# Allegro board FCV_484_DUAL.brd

Outline 347.98 x 322.58 mm; copper layers: TOP, SIG1, SIG2, SIG3, BOTTOM. Coordinates in mm from the lower left corner of the outline.
Outline path: rectangle 0,0 347.98,322.58

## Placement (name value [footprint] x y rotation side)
U1  -  [22X22]  173.99 168.17 0 top

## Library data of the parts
U1 = 22X22_0

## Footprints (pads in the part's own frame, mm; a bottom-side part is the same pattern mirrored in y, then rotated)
22X22
  round 0.401 smd: A1(-8.4,8.4) A2(-7.6,8.4) A3(-6.8,8.4) A4(-5.999,8.4) A5(-5.199,8.4) A6(-4.399,8.4) A7(-3.599,8.4) A8(-2.799,8.4) A9(-1.999,8.4) A10(-1.199,8.4) A11(-0.399,8.4) A12(0.399,8.4) A13(1.199,8.4) A14(1.999,8.4) A15(2.799,8.4) A16(3.599,8.4) A17(4.399,8.4) A18(5.199,8.4) A19(5.999,8.4) A20(6.8,8.4) A21(7.6,8.4) A22(8.4,8.4) AA1(-8.4,-7.6) AA2(-7.6,-7.6) AA3(-6.8,-7.6) AA4(-5.999,-7.6) AA5(-5.199,-7.6) AA6(-4.399,-7.6) AA7(-3.599,-7.6) AA8(-2.799,-7.6) AA9(-1.999,-7.6) AA10(-1.199,-7.6) AA11(-0.399,-7.6) AA12(0.399,-7.6) AA13(1.199,-7.6) AA14(1.999,-7.6) AA15(2.799,-7.6) AA16(3.599,-7.6) AA17(4.399,-7.6) AA18(5.199,-7.6) AA19(5.999,-7.6) AA20(6.8,-7.6) AA21(7.6,-7.6) AA22(8.4,-7.6) AB1(-8.4,-8.4) AB2(-7.6,-8.4) AB3(-6.8,-8.4) AB4(-5.999,-8.4) AB5(-5.199,-8.4) AB6(-4.399,-8.4) AB7(-3.599,-8.4) AB8(-2.799,-8.4) AB9(-1.999,-8.4) AB10(-1.199,-8.4) AB11(-0.399,-8.4) AB12(0.399,-8.4) AB13(1.199,-8.4) AB14(1.999,-8.4) AB15(2.799,-8.4) AB16(3.599,-8.4) AB17(4.399,-8.4) AB18(5.199,-8.4) AB19(5.999,-8.4) AB20(6.8,-8.4) AB21(7.6,-8.4) AB22(8.4,-8.4) B1(-8.4,7.6) B2(-7.6,7.6) B3(-6.8,7.6) B4(-5.999,7.6) B5(-5.199,7.6) B6(-4.399,7.6) B7(-3.599,7.6) B8(-2.799,7.6) B9(-1.999,7.6) B10(-1.199,7.6) B11(-0.399,7.6) B12(0.399,7.6) B13(1.199,7.6) B14(1.999,7.6) B15(2.799,7.6) B16(3.599,7.6) B17(4.399,7.6) B18(5.199,7.6) B19(5.999,7.6) B20(6.8,7.6) B21(7.6,7.6) B22(8.4,7.6) C1(-8.4,6.8) C2(-7.6,6.8) C3(-6.8,6.8) C4(-5.999,6.8) C5(-5.199,6.8) C6(-4.399,6.8) C7(-3.599,6.8) C8(-2.799,6.8) C9(-1.999,6.8) C10(-1.199,6.8) C11(-0.399,6.8) C12(0.399,6.8) C13(1.199,6.8) C14(1.999,6.8) C15(2.799,6.8) C16(3.599,6.8) C17(4.399,6.8) C18(5.199,6.8) C19(5.999,6.8) C20(6.8,6.8) C21(7.6,6.8) C22(8.4,6.8) D1(-8.4,5.999) D2(-7.6,5.999) D3(-6.8,5.999) D4(-5.999,5.999) D5(-5.199,5.999) D6(-4.399,5.999) D7(-3.599,5.999) D8(-2.799,5.999) D9(-1.999,5.999) D10(-1.199,5.999) D11(-0.399,5.999) D12(0.399,5.999) D13(1.199,5.999) D14(1.999,5.999) D15(2.799,5.999) D16(3.599,5.999) D17(4.399,5.999) D18(5.199,5.999) D19(5.999,5.999) D20(6.8,5.999) D21(7.6,5.999) D22(8.4,5.999) E1(-8.4,5.199) E2(-7.6,5.199) E3(-6.8,5.199) E4(-5.999,5.199) E5(-5.199,5.199) E6(-4.399,5.199) E7(-3.599,5.199) E8(-2.799,5.199) E9(-1.999,5.199) E10(-1.199,5.199) E11(-0.399,5.199) E12(0.399,5.199) E13(1.199,5.199) E14(1.999,5.199) E15(2.799,5.199) E16(3.599,5.199) E17(4.399,5.199) E18(5.199,5.199) E19(5.999,5.199) E20(6.8,5.199) E21(7.6,5.199) E22(8.4,5.199) F1(-8.4,4.399) F2(-7.6,4.399) F3(-6.8,4.399) F4(-5.999,4.399) F5(-5.199,4.399) F6(-4.399,4.399) F7(-3.599,4.399) F8(-2.799,4.399) F9(-1.999,4.399) F10(-1.199,4.399) F11(-0.399,4.399) F12(0.399,4.399) F13(1.199,4.399) F14(1.999,4.399) F15(2.799,4.399) F16(3.599,4.399) F17(4.399,4.399) F18(5.199,4.399) F19(5.999,4.399) F20(6.8,4.399) F21(7.6,4.399) F22(8.4,4.399) G1(-8.4,3.599) G2(-7.6,3.599) G3(-6.8,3.599) G4(-5.999,3.599) G5(-5.199,3.599) G6(-4.399,3.599) G7(-3.599,3.599) G8(-2.799,3.599) G9(-1.999,3.599) G10(-1.199,3.599) G11(-0.399,3.599) G12(0.399,3.599) G13(1.199,3.599) G14(1.999,3.599) G15(2.799,3.599) G16(3.599,3.599) G17(4.399,3.599) G18(5.199,3.599) G19(5.999,3.599) G20(6.8,3.599) G21(7.6,3.599) G22(8.4,3.599) H1(-8.4,2.799) H2(-7.6,2.799) H3(-6.8,2.799) H4(-5.999,2.799) H5(-5.199,2.799) H6(-4.399,2.799) H7(-3.599,2.799) H8(-2.799,2.799) H9(-1.999,2.799) H10(-1.199,2.799) H11(-0.399,2.799) H12(0.399,2.799) H13(1.199,2.799) H14(1.999,2.799) H15(2.799,2.799) H16(3.599,2.799) H17(4.399,2.799) H18(5.199,2.799) H19(5.999,2.799) H20(6.8,2.799) H21(7.6,2.799) H22(8.4,2.799) J1(-8.4,1.999) J2(-7.6,1.999) J3(-6.8,1.999) J4(-5.999,1.999) J5(-5.199,1.999) J6(-4.399,1.999) J7(-3.599,1.999) J8(-2.799,1.999) J9(-1.999,1.999) J10(-1.199,1.999) J11(-0.399,1.999) J12(0.399,1.999) J13(1.199,1.999) J14(1.999,1.999) J15(2.799,1.999) J16(3.599,1.999) J17(4.399,1.999) J18(5.199,1.999) J19(5.999,1.999) J20(6.8,1.999) J21(7.6,1.999) J22(8.4,1.999) K1(-8.4,1.199) K2(-7.6,1.199) K3(-6.8,1.199) K4(-5.999,1.199) K5(-5.199,1.199) K6(-4.399,1.199) K7(-3.599,1.199) K8(-2.799,1.199) K9(-1.999,1.199) K10(-1.199,1.199) K11(-0.399,1.199) K12(0.399,1.199) K13(1.199,1.199) K14(1.999,1.199) K15(2.799,1.199) K16(3.599,1.199) K17(4.399,1.199) K18(5.199,1.199) K19(5.999,1.199) K20(6.8,1.199) K21(7.6,1.199) K22(8.4,1.199) L1(-8.4,0.399) L2(-7.6,0.399) L3(-6.8,0.399) L4(-5.999,0.399) L5(-5.199,0.399) L6(-4.399,0.399) L7(-3.599,0.399) L8(-2.799,0.399) L9(-1.999,0.399) L10(-1.199,0.399) L11(-0.399,0.399) L12(0.399,0.399) L13(1.199,0.399) L14(1.999,0.399) L15(2.799,0.399) L16(3.599,0.399) L17(4.399,0.399) L18(5.199,0.399) L19(5.999,0.399) L20(6.8,0.399) L21(7.6,0.399) L22(8.4,0.399) M1(-8.4,-0.399) M2(-7.6,-0.399) M3(-6.8,-0.399) M4(-5.999,-0.399) M5(-5.199,-0.399) M6(-4.399,-0.399) M7(-3.599,-0.399) M8(-2.799,-0.399) M9(-1.999,-0.399) M10(-1.199,-0.399) M11(-0.399,-0.399) M12(0.399,-0.399) M13(1.199,-0.399) M14(1.999,-0.399) M15(2.799,-0.399) M16(3.599,-0.399) M17(4.399,-0.399) M18(5.199,-0.399) M19(5.999,-0.399) M20(6.8,-0.399) M21(7.6,-0.399) M22(8.4,-0.399) N1(-8.4,-1.199) N2(-7.6,-1.199) N3(-6.8,-1.199) N4(-5.999,-1.199) N5(-5.199,-1.199) N6(-4.399,-1.199) N7(-3.599,-1.199) N8(-2.799,-1.199) N9(-1.999,-1.199) N10(-1.199,-1.199) N11(-0.399,-1.199) N12(0.399,-1.199) N13(1.199,-1.199) N14(1.999,-1.199) N15(2.799,-1.199) N16(3.599,-1.199) N17(4.399,-1.199) N18(5.199,-1.199) N19(5.999,-1.199) N20(6.8,-1.199) N21(7.6,-1.199) N22(8.4,-1.199) P1(-8.4,-1.999) P2(-7.6,-1.999) P3(-6.8,-1.999) P4(-5.999,-1.999) P5(-5.199,-1.999) P6(-4.399,-1.999) P7(-3.599,-1.999) P8(-2.799,-1.999) P9(-1.999,-1.999) P10(-1.199,-1.999) P11(-0.399,-1.999) P12(0.399,-1.999) P13(1.199,-1.999) P14(1.999,-1.999) P15(2.799,-1.999) P16(3.599,-1.999) P17(4.399,-1.999) P18(5.199,-1.999) P19(5.999,-1.999) P20(6.8,-1.999) P21(7.6,-1.999) P22(8.4,-1.999) R1(-8.4,-2.799) R2(-7.6,-2.799) R3(-6.8,-2.799) R4(-5.999,-2.799) R5(-5.199,-2.799) R6(-4.399,-2.799) R7(-3.599,-2.799) R8(-2.799,-2.799) R9(-1.999,-2.799) R10(-1.199,-2.799) R11(-0.399,-2.799) R12(0.399,-2.799) R13(1.199,-2.799) R14(1.999,-2.799) R15(2.799,-2.799) R16(3.599,-2.799) R17(4.399,-2.799) R18(5.199,-2.799) R19(5.999,-2.799) R20(6.8,-2.799) R21(7.6,-2.799) R22(8.4,-2.799) T1(-8.4,-3.599) T2(-7.6,-3.599) T3(-6.8,-3.599) T4(-5.999,-3.599) T5(-5.199,-3.599) T6(-4.399,-3.599) T7(-3.599,-3.599) T8(-2.799,-3.599) T9(-1.999,-3.599) T10(-1.199,-3.599) T11(-0.399,-3.599) T12(0.399,-3.599) T13(1.199,-3.599) T14(1.999,-3.599) T15(2.799,-3.599) T16(3.599,-3.599) T17(4.399,-3.599) T18(5.199,-3.599) T19(5.999,-3.599) T20(6.8,-3.599) T21(7.6,-3.599) T22(8.4,-3.599) U1(-8.4,-4.399) U2(-7.6,-4.399) U3(-6.8,-4.399) U4(-5.999,-4.399) U5(-5.199,-4.399) U6(-4.399,-4.399) U7(-3.599,-4.399) U8(-2.799,-4.399) U9(-1.999,-4.399) U10(-1.199,-4.399) U11(-0.399,-4.399) U12(0.399,-4.399) U13(1.199,-4.399) U14(1.999,-4.399) U15(2.799,-4.399) U16(3.599,-4.399) U17(4.399,-4.399) U18(5.199,-4.399) U19(5.999,-4.399) U20(6.8,-4.399) U21(7.6,-4.399) U22(8.4,-4.399) V1(-8.4,-5.199) V2(-7.6,-5.199) V3(-6.8,-5.199) V4(-5.999,-5.199) V5(-5.199,-5.199) V6(-4.399,-5.199) V7(-3.599,-5.199) V8(-2.799,-5.199) V9(-1.999,-5.199) V10(-1.199,-5.199) V11(-0.399,-5.199) V12(0.399,-5.199) V13(1.199,-5.199) V14(1.999,-5.199) V15(2.799,-5.199) V16(3.599,-5.199) V17(4.399,-5.199) V18(5.199,-5.199) V19(5.999,-5.199) V20(6.8,-5.199) V21(7.6,-5.199) V22(8.4,-5.199) W1(-8.4,-5.999) W2(-7.6,-5.999) W3(-6.8,-5.999) W4(-5.999,-5.999) W5(-5.199,-5.999) W6(-4.399,-5.999) W7(-3.599,-5.999) W8(-2.799,-5.999) W9(-1.999,-5.999) W10(-1.199,-5.999) W11(-0.399,-5.999) W12(0.399,-5.999) W13(1.199,-5.999) W14(1.999,-5.999) W15(2.799,-5.999) W16(3.599,-5.999) W17(4.399,-5.999) W18(5.199,-5.999) W19(5.999,-5.999) W20(6.8,-5.999) W21(7.6,-5.999) W22(8.4,-5.999) Y1(-8.4,-6.8) Y2(-7.6,-6.8) Y3(-6.8,-6.8) Y4(-5.999,-6.8) Y5(-5.199,-6.8) Y6(-4.399,-6.8) Y7(-3.599,-6.8) Y8(-2.799,-6.8) Y9(-1.999,-6.8) Y10(-1.199,-6.8) Y11(-0.399,-6.8) Y12(0.399,-6.8) Y13(1.199,-6.8) Y14(1.999,-6.8) Y15(2.799,-6.8) Y16(3.599,-6.8) Y17(4.399,-6.8) Y18(5.199,-6.8) Y19(5.999,-6.8) Y20(6.8,-6.8) Y21(7.6,-6.8) Y22(8.4,-6.8)

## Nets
VDD: U1.J13(VDD#J13) U1.K12(VDD#K12) U1.K14(VDD#K14) U1.K16(VDD#K16) U1.L11(VDD#L11) U1.L15(VDD#L15) U1.L17(VDD#L17) U1.M12(VDD#M12) U1.M14(VDD#M14) U1.M16(VDD#M16) U1.N11(VDD#N11) U1.N13(VDD#N13) U1.N15(VDD#N15) U1.N17(VDD#N17)
VDD18: U1.N14(VDD18#N14) U1.P10(VDD18#P10) U1.P12(VDD18#P12) U1.P14(VDD18#P14) U1.P16(VDD18#P16)
VDD25: U1.H8(VDD25#H8) U1.J17(VDD25#J17) U1.L13(VDD25#L13) U1.R9(VDD25#R9) U1.R17(VDD25#R17)
VDDA: U1.G21(VDDA#G21) U1.J21(VDDA#J21) U1.K19(VDDA#K19) U1.L21(VDDA#L21) U1.N21(VDDA#N21) U1.P19(VDDA#P19) U1.R21(VDDA#R21)
VDDA25: U1.J18(VDDA25#J18) U1.N18(VDDA25#N18)
VDDAUX2: U1.H11(VDDAUX2#H11) U1.H14(VDDAUX2#H14) U1.H16(VDDAUX2#H16) U1.J15(VDDAUX2#J15)
VDDAUX4: U1.F4(VDDAUX4#F4) U1.G1(VDDAUX4#G1) U1.K10(VDDAUX4#K10) U1.M10(VDDAUX4#M10) U1.N9(VDDAUX4#N9)
VDDI0: U1.AA9(VDDI0#AA9) U1.AB6(VDDI0#AB6) U1.U1(VDDI0#U1) U1.U11(VDDI0#U11) U1.V8(VDDI0#V8) U1.W5(VDDI0#W5) U1.Y2(VDDI0#Y2)
VDDI1: U1.AA19(VDDI1#AA19) U1.AB16(VDDI1#AB16) U1.T14(VDDI1#T14) U1.V18(VDDI1#V18) U1.W15(VDDI1#W15) U1.Y12(VDDI1#Y12) U1.Y22(VDDI1#Y22)
VDDI2: U1.A9(VDDI2#A9) U1.A19(VDDI2#A19) U1.B6(VDDI2#B6) U1.B16(VDDI2#B16) U1.C3(VDDI2#C3) U1.C13(VDDI2#C13) U1.C21(VDDI2#C21) U1.D10(VDDI2#D10) U1.E7(VDDI2#E7) U1.E17(VDDI2#E17) U1.F14(VDDI2#F14) U1.H13(VDDI2#H13) U1.H17(VDDI2#H17)
VDDI3: U1.G11(VDDI3#G11) U1.J11(VDDI3#J11)
VDDI4: U1.J5(VDDI4#J5) U1.K2(VDDI4#K2) U1.L9(VDDI4#L9) U1.M6(VDDI4#M6) U1.N3(VDDI4#N3) U1.R7(VDDI4#R7) U1.T4(VDDI4#T4)
VDDSREF: U1.L18(VDDSREF#L18) U1.R18(VDDSREF#R18)
VSS: U1.A1(VSS#A1) U1.A4(VSS#A4) U1.A14(VSS#A14) U1.A22(VSS#A22) U1.AA4(VSS#AA4) U1.AA14(VSS#AA14) U1.AB1(VSS#AB1) U1.AB11(VSS#AB11) U1.AB22(VSS#AB22) U1.B11(VSS#B11) U1.C8(VSS#C8) U1.C18(VSS#C18) U1.D5(VSS#D5) U1.D15(VSS#D15) U1.E2(VSS#E2) U1.E12(VSS#E12) U1.F9(VSS#F9) U1.G6(VSS#G6) U1.G16(VSS#G16) U1.H3(VSS#H3) U1.J10(VSS#J10) U1.J12(VSS#J12) U1.J14(VSS#J14) U1.J16(VSS#J16) U1.K7(VSS#K7) U1.K11(VSS#K11) U1.K13(VSS#K13) U1.K15(VSS#K15) U1.K17(VSS#K17) U1.L4(VSS#L4) U1.L10(VSS#L10) U1.L12(VSS#L12) U1.L14(VSS#L14) U1.L16(VSS#L16) U1.M1(VSS#M1) U1.M11(VSS#M11) U1.M13(VSS#M13) U1.M15(VSS#M15) U1.M17(VSS#M17) U1.N10(VSS#N10) U1.N12(VSS#N12) U1.N16(VSS#N16) U1.P5(VSS#P5) U1.P11(VSS#P11) U1.P13(VSS#P13) U1.P15(VSS#P15) U1.P17(VSS#P17) U1.R2(VSS#R2) U1.T9(VSS#T9) U1.U6(VSS#U6) U1.U16(VSS#U16) U1.V3(VSS#V3) U1.V13(VSS#V13) U1.W10(VSS#W10) U1.W20(VSS#W20) U1.Y7(VSS#Y7) U1.Y17(VSS#Y17)
VSSA: U1.E20(VSSA#E20) U1.E21(VSSA#E21) U1.E22(VSSA#E22) U1.F18(VSSA#F18) U1.F19(VSSA#F19) U1.F20(VSSA#F20) U1.G18(VSSA#G18) U1.G22(VSSA#G22) U1.H20(VSSA#H20) U1.J22(VSSA#J22) U1.K18(VSSA#K18) U1.K20(VSSA#K20) U1.L22(VSSA#L22) U1.M18(VSSA#M18) U1.M19(VSSA#M19) U1.M20(VSSA#M20) U1.N22(VSSA#N22) U1.P18(VSSA#P18) U1.P20(VSSA#P20) U1.R22(VSSA#R22) U1.T18(VSSA#T18) U1.T19(VSSA#T19) U1.T20(VSSA#T20) U1.U20(VSSA#U20) U1.U21(VSSA#U21) U1.U22(VSSA#U22)
IO-BANK0_1: U1.R10(IO-BANK0_1)
IO-BANK0_2: U1.R11(IO-BANK0_2)
IO-BANK0_3: U1.R12(IO-BANK0_3)
IO-BANK0_4: U1.T6(IO-BANK0_4)
IO-BANK0_5: U1.T7(IO-BANK0_5)
IO-BANK0_6: U1.T8(IO-BANK0_6)
IO-BANK0_7: U1.T10(IO-BANK0_7)
IO-BANK0_8: U1.T11(IO-BANK0_8)
IO-BANK0_9: U1.U2(IO-BANK0_9)
IO-BANK0_10: U1.U3(IO-BANK0_10)
IO-BANK0_11: U1.U4(IO-BANK0_11)
IO-BANK0_12: U1.U5(IO-BANK0_12)
IO-BANK0_13: U1.U7(IO-BANK0_13)
IO-BANK0_14: U1.U8(IO-BANK0_14)
IO-BANK0_15: U1.U9(IO-BANK0_15)
IO-BANK0_16: U1.U10(IO-BANK0_16)
IO-BANK0_17: U1.V1(IO-BANK0_17)
IO-BANK0_18: U1.V2(IO-BANK0_18)
IO-BANK0_19: U1.V4(IO-BANK0_19)
IO-BANK0_20: U1.V5(IO-BANK0_20)
IO-BANK0_21: U1.V6(IO-BANK0_21)
IO-BANK0_22: U1.V7(IO-BANK0_22)
IO-BANK0_23: U1.V9(IO-BANK0_23)
IO-BANK0_24: U1.V10(IO-BANK0_24)
IO-BANK0_25: U1.V11(IO-BANK0_25)
IO-BANK0_26: U1.W1(IO-BANK0_26)
IO-BANK0_27: U1.W2(IO-BANK0_27)
IO-BANK0_28: U1.W3(IO-BANK0_28)
IO-BANK0_29: U1.W4(IO-BANK0_29)
IO-BANK0_30: U1.W6(IO-BANK0_30)
IO-BANK0_31: U1.W7(IO-BANK0_31)
IO-BANK0_32: U1.W8(IO-BANK0_32)
IO-BANK0_33: U1.W9(IO-BANK0_33)
IO-BANK0_34: U1.W11(IO-BANK0_34)
IO-BANK0_35: U1.Y1(IO-BANK0_35)
IO-BANK0_36: U1.Y3(IO-BANK0_36)
IO-BANK0_37: U1.Y4(IO-BANK0_37)
IO-BANK0_38: U1.Y5(IO-BANK0_38)
IO-BANK0_39: U1.Y6(IO-BANK0_39)
IO-BANK0_40: U1.Y8(IO-BANK0_40)
IO-BANK0_41: U1.Y9(IO-BANK0_41)
IO-BANK0_42: U1.Y10(IO-BANK0_42)
IO-BANK0_43: U1.Y11(IO-BANK0_43)
IO-BANK0_44: U1.AA1(IO-BANK0_44)
IO-BANK0_45: U1.AA2(IO-BANK0_45)
IO-BANK0_46: U1.AA3(IO-BANK0_46)
IO-BANK0_47: U1.AA5(IO-BANK0_47)
IO-BANK0_48: U1.AA6(IO-BANK0_48)
IO-BANK0_49: U1.AA7(IO-BANK0_49)
IO-BANK0_50: U1.AA8(IO-BANK0_50)
IO-BANK0_51: U1.AA10(IO-BANK0_51)
IO-BANK0_52: U1.AA11(IO-BANK0_52)
IO-BANK0_53: U1.AB2(IO-BANK0_53)
IO-BANK0_54: U1.AB3(IO-BANK0_54)
IO-BANK0_55: U1.AB4(IO-BANK0_55)
IO-BANK0_56: U1.AB5(IO-BANK0_56)
IO-BANK0_57: U1.AB7(IO-BANK0_57)
IO-BANK0_58: U1.AB8(IO-BANK0_58)
IO-BANK0_59: U1.AB9(IO-BANK0_59)
IO-BANK0_60: U1.AB10(IO-BANK0_60)
IO-BANK1_1: U1.R13(IO-BANK1_1)
IO-BANK1_2: U1.R14(IO-BANK1_2)
IO-BANK1_3: U1.R15(IO-BANK1_3)
IO-BANK1_4: U1.R16(IO-BANK1_4)
IO-BANK1_5: U1.T12(IO-BANK1_5)
IO-BANK1_6: U1.T13(IO-BANK1_6)
IO-BANK1_7: U1.T15(IO-BANK1_7)
IO-BANK1_8: U1.T16(IO-BANK1_8)
IO-BANK1_9: U1.T17(IO-BANK1_9)
IO-BANK1_10: U1.U12(IO-BANK1_10)
IO-BANK1_11: U1.U13(IO-BANK1_11)
IO-BANK1_12: U1.U14(IO-BANK1_12)
IO-BANK1_13: U1.U15(IO-BANK1_13)
IO-BANK1_14: U1.U17(IO-BANK1_14)
IO-BANK1_15: U1.U18(IO-BANK1_15)
IO-BANK1_16: U1.U19(IO-BANK1_16)
IO-BANK1_17: U1.V12(IO-BANK1_17)
IO-BANK1_18: U1.V14(IO-BANK1_18)
IO-BANK1_19: U1.V15(IO-BANK1_19)
IO-BANK1_20: U1.V16(IO-BANK1_20)
IO-BANK1_21: U1.V17(IO-BANK1_21)
IO-BANK1_22: U1.V19(IO-BANK1_22)
IO-BANK1_23: U1.V20(IO-BANK1_23)
IO-BANK1_24: U1.V21(IO-BANK1_24)
IO-BANK1_25: U1.V22(IO-BANK1_25)
IO-BANK1_26: U1.W12(IO-BANK1_26)
IO-BANK1_27: U1.W13(IO-BANK1_27)
IO-BANK1_28: U1.W14(IO-BANK1_28)
IO-BANK1_29: U1.W16(IO-BANK1_29)
IO-BANK1_30: U1.W17(IO-BANK1_30)
IO-BANK1_31: U1.W18(IO-BANK1_31)
IO-BANK1_32: U1.W19(IO-BANK1_32)
IO-BANK1_33: U1.W21(IO-BANK1_33)
IO-BANK1_34: U1.W22(IO-BANK1_34)
IO-BANK1_35: U1.Y13(IO-BANK1_35)
IO-BANK1_36: U1.Y14(IO-BANK1_36)
IO-BANK1_37: U1.Y15(IO-BANK1_37)
IO-BANK1_38: U1.Y16(IO-BANK1_38)
IO-BANK1_39: U1.Y18(IO-BANK1_39)
IO-BANK1_40: U1.Y19(IO-BANK1_40)
IO-BANK1_41: U1.Y20(IO-BANK1_41)
IO-BANK1_42: U1.Y21(IO-BANK1_42)
IO-BANK1_43: U1.AA12(IO-BANK1_43)
IO-BANK1_44: U1.AA13(IO-BANK1_44)
IO-BANK1_45: U1.AA15(IO-BANK1_45)
IO-BANK1_46: U1.AA16(IO-BANK1_46)
IO-BANK1_47: U1.AA17(IO-BANK1_47)
IO-BANK1_48: U1.AA18(IO-BANK1_48)
IO-BANK1_49: U1.AA20(IO-BANK1_49)
IO-BANK1_50: U1.AA21(IO-BANK1_50)
IO-BANK1_51: U1.AA22(IO-BANK1_51)
IO-BANK1_52: U1.AB12(IO-BANK1_52)
IO-BANK1_53: U1.AB13(IO-BANK1_53)
IO-BANK1_54: U1.AB14(IO-BANK1_54)
IO-BANK1_55: U1.AB15(IO-BANK1_55)
IO-BANK1_56: U1.AB17(IO-BANK1_56)
IO-BANK1_57: U1.AB18(IO-BANK1_57)
IO-BANK1_58: U1.AB19(IO-BANK1_58)
IO-BANK1_59: U1.AB20(IO-BANK1_59)
IO-BANK1_60: U1.AB21(IO-BANK1_60)
IO-BANK2_1: U1.A2(IO-BANK2_1)
IO-BANK2_2: U1.A3(IO-BANK2_2)
IO-BANK2_3: U1.A5(IO-BANK2_3)
IO-BANK2_4: U1.A6(IO-BANK2_4)
IO-BANK2_5: U1.A7(IO-BANK2_5)
IO-BANK2_6: U1.A8(IO-BANK2_6)
IO-BANK2_7: U1.A10(IO-BANK2_7)
IO-BANK2_8: U1.A11(IO-BANK2_8)
IO-BANK2_9: U1.A12(IO-BANK2_9)
IO-BANK2_10: U1.A13(IO-BANK2_10)
IO-BANK2_11: U1.A15(IO-BANK2_11)
IO-BANK2_12: U1.A16(IO-BANK2_12)
IO-BANK2_13: U1.A17(IO-BANK2_13)
IO-BANK2_14: U1.A18(IO-BANK2_14)
IO-BANK2_15: U1.A20(IO-BANK2_15)
IO-BANK2_16: U1.A21(IO-BANK2_16)
IO-BANK2_17: U1.B1(IO-BANK2_17)
IO-BANK2_18: U1.B2(IO-BANK2_18)
IO-BANK2_19: U1.B3(IO-BANK2_19)
IO-BANK2_20: U1.B4(IO-BANK2_20)
IO-BANK2_21: U1.B5(IO-BANK2_21)
IO-BANK2_22: U1.B7(IO-BANK2_22)
IO-BANK2_23: U1.B8(IO-BANK2_23)
IO-BANK2_24: U1.B9(IO-BANK2_24)
IO-BANK2_25: U1.B10(IO-BANK2_25)
IO-BANK2_26: U1.B12(IO-BANK2_26)
IO-BANK2_27: U1.B13(IO-BANK2_27)
IO-BANK2_28: U1.B14(IO-BANK2_28)
IO-BANK2_29: U1.B15(IO-BANK2_29)
IO-BANK2_30: U1.B17(IO-BANK2_30)
IO-BANK2_31: U1.B18(IO-BANK2_31)
IO-BANK2_32: U1.B19(IO-BANK2_32)
IO-BANK2_33: U1.B20(IO-BANK2_33)
IO-BANK2_34: U1.B21(IO-BANK2_34)
IO-BANK2_35: U1.B22(IO-BANK2_35)
IO-BANK2_36: U1.C1(IO-BANK2_36)
IO-BANK2_37: U1.C2(IO-BANK2_37)
IO-BANK2_38: U1.C4(IO-BANK2_38)
IO-BANK2_39: U1.C5(IO-BANK2_39)
IO-BANK2_40: U1.C6(IO-BANK2_40)
IO-BANK2_41: U1.C7(IO-BANK2_41)
IO-BANK2_42: U1.C9(IO-BANK2_42)
IO-BANK2_43: U1.C10(IO-BANK2_43)
IO-BANK2_44: U1.C11(IO-BANK2_44)
IO-BANK2_45: U1.C12(IO-BANK2_45)
IO-BANK2_46: U1.C14(IO-BANK2_46)
IO-BANK2_47: U1.C15(IO-BANK2_47)
IO-BANK2_48: U1.C16(IO-BANK2_48)
IO-BANK2_49: U1.C17(IO-BANK2_49)
IO-BANK2_50: U1.C19(IO-BANK2_50)
IO-BANK2_51: U1.C20(IO-BANK2_51)
IO-BANK2_52: U1.C22(IO-BANK2_52)
IO-BANK2_53: U1.D3(IO-BANK2_53)
IO-BANK2_54: U1.D4(IO-BANK2_54)
IO-BANK2_55: U1.D6(IO-BANK2_55)
IO-BANK2_56: U1.D7(IO-BANK2_56)
IO-BANK2_57: U1.D8(IO-BANK2_57)
IO-BANK2_58: U1.D9(IO-BANK2_58)
IO-BANK2_59: U1.D11(IO-BANK2_59)
IO-BANK2_60: U1.D12(IO-BANK2_60)
IO-BANK2_61: U1.D13(IO-BANK2_61)
IO-BANK2_62: U1.D14(IO-BANK2_62)
IO-BANK2_63: U1.D16(IO-BANK2_63)
IO-BANK2_64: U1.D17(IO-BANK2_64)
IO-BANK2_65: U1.D18(IO-BANK2_65)
IO-BANK2_66: U1.D19(IO-BANK2_66)
IO-BANK2_67: U1.D20(IO-BANK2_67)
IO-BANK2_68: U1.D21(IO-BANK2_68)
IO-BANK2_69: U1.D22(IO-BANK2_69)
IO-BANK2_70: U1.E4(IO-BANK2_70)
IO-BANK2_71: U1.E5(IO-BANK2_71)
IO-BANK2_72: U1.E6(IO-BANK2_72)
IO-BANK2_73: U1.E8(IO-BANK2_73)
IO-BANK2_74: U1.E9(IO-BANK2_74)
IO-BANK2_75: U1.E10(IO-BANK2_75)
IO-BANK2_76: U1.E11(IO-BANK2_76)
IO-BANK2_77: U1.E13(IO-BANK2_77)
IO-BANK2_78: U1.E14(IO-BANK2_78)
IO-BANK2_79: U1.E15(IO-BANK2_79)
IO-BANK2_80: U1.E16(IO-BANK2_80)
IO-BANK2_81: U1.E18(IO-BANK2_81)
IO-BANK2_82: U1.E19(IO-BANK2_82)
IO-BANK2_83: U1.F10(IO-BANK2_83)
IO-BANK2_84: U1.F11(IO-BANK2_84)
IO-BANK2_85: U1.F12(IO-BANK2_85)
IO-BANK2_86: U1.F13(IO-BANK2_86)
IO-BANK2_87: U1.F15(IO-BANK2_87)
IO-BANK2_88: U1.F16(IO-BANK2_88)
IO-BANK2_89: U1.F17(IO-BANK2_89)
IO-BANK2_90: U1.G12(IO-BANK2_90)
IO-BANK2_91: U1.G13(IO-BANK2_91)
IO-BANK2_92: U1.G14(IO-BANK2_92)
IO-BANK2_93: U1.G15(IO-BANK2_93)
IO-BANK2_94: U1.G17(IO-BANK2_94)
IO-BANK2_95: U1.H12(IO-BANK2_95)
IO-BANK2_96: U1.H15(IO-BANK2_96)
IO-BANK4_1: U1.H1(IO-BANK4_1)
IO-BANK4_2: U1.H2(IO-BANK4_2)
IO-BANK4_3: U1.J1(IO-BANK4_3)
IO-BANK4_4: U1.J2(IO-BANK4_4)
IO-BANK4_5: U1.J3(IO-BANK4_5)
IO-BANK4_6: U1.J4(IO-BANK4_6)
IO-BANK4_7: U1.J6(IO-BANK4_7)
IO-BANK4_8: U1.J7(IO-BANK4_8)
IO-BANK4_9: U1.J8(IO-BANK4_9)
IO-BANK4_10: U1.J9(IO-BANK4_10)
IO-BANK4_11: U1.K1(IO-BANK4_11)
IO-BANK4_12: U1.K3(IO-BANK4_12)
IO-BANK4_13: U1.K4(IO-BANK4_13)
IO-BANK4_14: U1.K5(IO-BANK4_14)
IO-BANK4_15: U1.K6(IO-BANK4_15)
IO-BANK4_16: U1.K8(IO-BANK4_16)
IO-BANK4_17: U1.K9(IO-BANK4_17)
IO-BANK4_18: U1.L1(IO-BANK4_18)
IO-BANK4_19: U1.L2(IO-BANK4_19)
IO-BANK4_20: U1.L3(IO-BANK4_20)
IO-BANK4_21: U1.L5(IO-BANK4_21)
IO-BANK4_22: U1.L6(IO-BANK4_22)
IO-BANK4_23: U1.L7(IO-BANK4_23)
IO-BANK4_24: U1.L8(IO-BANK4_24)
IO-BANK4_25: U1.M2(IO-BANK4_25)
IO-BANK4_26: U1.M3(IO-BANK4_26)
IO-BANK4_27: U1.M4(IO-BANK4_27)
IO-BANK4_28: U1.M5(IO-BANK4_28)
IO-BANK4_29: U1.M7(IO-BANK4_29)
IO-BANK4_30: U1.M8(IO-BANK4_30)
IO-BANK4_31: U1.M9(IO-BANK4_31)
IO-BANK4_32: U1.N1(IO-BANK4_32)
IO-BANK4_33: U1.N2(IO-BANK4_33)
IO-BANK4_34: U1.N4(IO-BANK4_34)
IO-BANK4_35: U1.N5(IO-BANK4_35)
IO-BANK4_36: U1.N6(IO-BANK4_36)
IO-BANK4_37: U1.N7(IO-BANK4_37)
IO-BANK4_38: U1.N8(IO-BANK4_38)
IO-BANK4_39: U1.P1(IO-BANK4_39)
IO-BANK4_40: U1.P2(IO-BANK4_40)
IO-BANK4_41: U1.P3(IO-BANK4_41)
IO-BANK4_42: U1.P4(IO-BANK4_42)
IO-BANK4_43: U1.P6(IO-BANK4_43)
IO-BANK4_44: U1.P7(IO-BANK4_44)
IO-BANK4_45: U1.P8(IO-BANK4_45)
IO-BANK4_46: U1.P9(IO-BANK4_46)
IO-BANK4_47: U1.R1(IO-BANK4_47)
IO-BANK4_48: U1.R3(IO-BANK4_48)
IO-BANK4_49: U1.R4(IO-BANK4_49)
IO-BANK4_50: U1.R5(IO-BANK4_50)
IO-BANK4_51: U1.R6(IO-BANK4_51)
IO-BANK4_52: U1.R8(IO-BANK4_52)
IO-BANK4_53: U1.T1(IO-BANK4_53)
IO-BANK4_54: U1.T2(IO-BANK4_54)
IO-BANK4_55: U1.T3(IO-BANK4_55)
IO-BANK4_56: U1.T5(IO-BANK4_56)
IO-BANK5_1: U1.D1(IO-BANK5_1)
IO-BANK5_2: U1.D2(IO-BANK5_2)
IO-BANK5_3: U1.E1(IO-BANK5_3)
IO-BANK5_4: U1.E3(IO-BANK5_4)
IO-BANK5_5: U1.F1(IO-BANK5_5)
IO-BANK5_6: U1.F2(IO-BANK5_6)
IO-BANK5_7: U1.F3(IO-BANK5_7)
IO-BANK5_8: U1.F5(IO-BANK5_8)
IO-BANK5_9: U1.G2(IO-BANK5_9)
IO-BANK5_10: U1.G3(IO-BANK5_10)
IO-BANK5_11: U1.G4(IO-BANK5_11)
IO-BANK5_12: U1.G5(IO-BANK5_12)
JTAG-IO_1: U1.F6(JTAG-IO_1)
JTAG-IO_2: U1.F7(JTAG-IO_2)
JTAG-IO_3: U1.F8(JTAG-IO_3)
JTAG-IO_4: U1.G7(JTAG-IO_4)
JTAG-IO_5: U1.G8(JTAG-IO_5)
JTAG-IO_6: U1.G9(JTAG-IO_6)
JTAG-IO_7: U1.G10(JTAG-IO_7)
JTAG-IO_8: U1.H4(JTAG-IO_8)
JTAG-IO_9: U1.H5(JTAG-IO_9)
JTAG-IO_10: U1.H6(JTAG-IO_10)
JTAG-IO_11: U1.H7(JTAG-IO_11)
JTAG-IO_12: U1.H9(JTAG-IO_12)
JTAG-IO_13: U1.H10(JTAG-IO_13)
REFCLK0_1: U1.N19(REFCLK0_1)
REFCLK0_2: U1.N20(REFCLK0_2)
REFCLK1_1: U1.L19(REFCLK1_1)
REFCLK1_2: U1.L20(REFCLK1_2)
REFCLK2_1: U1.J19(REFCLK2_1)
REFCLK2_2: U1.J20(REFCLK2_2)
RX0_1: U1.R19(RX0_1)
RX0_2: U1.R20(RX0_2)
RX1_1: U1.M21(RX1_1)
RX1_2: U1.M22(RX1_2)
RX2_1: U1.K21(RX2_1)
RX2_2: U1.K22(RX2_2)
RX3_1: U1.G19(RX3_1)
RX3_2: U1.G20(RX3_2)
SERDES_VREF: U1.H18(SERDES_VREF#H18) U1.H19(SERDES_VREF#H19)
TX0_1: U1.T21(TX0_1)
TX0_2: U1.T22(TX0_2)
TX1_1: U1.P21(TX1_1)
TX1_2: U1.P22(TX1_2)
TX2_1: U1.H21(TX2_1)
TX2_2: U1.H22(TX2_2)
TX3_1: U1.F21(TX3_1)
TX3_2: U1.F22(TX3_2)

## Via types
v1: diameter 0.457, hole 0.254, TOP to BOTTOM, 312 vias

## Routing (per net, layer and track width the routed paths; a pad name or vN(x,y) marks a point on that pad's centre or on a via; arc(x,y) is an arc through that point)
VDD: length 7.9
  TOP w0.381: U1.L15 v1(177.19,168.97) ; U1.M14 v1(176.39,167.37) ; U1.J13 v1(175.59,170.57) ; U1.L17 v1(178.79,168.97) ; U1.N13 v1(175.59,166.57) ; U1.K12 v1(174.79,169.77) ; U1.N15 v1(177.19,166.57) ; U1.N11 v1(173.19,166.57) ; U1.N17 v1(178.79,166.57) ; U1.L11 v1(173.19,168.97) ; U1.K14 v1(176.39,169.77) ; U1.M16 v1(177.99,167.37) ; U1.M12 v1(174.79,167.37) ; U1.K16 v1(177.99,169.77)
VDD18: length 2.8
  TOP w0.381: U1.P10 v1(172.39,165.77) ; U1.N14 v1(176.39,166.57) ; U1.P12 v1(174.79,165.77) ; U1.P16 v1(177.99,165.77) ; U1.P14 v1(176.39,165.77)
VDD25: length 2.8
  TOP w0.381: U1.R17 v1(178.79,164.97) ; U1.L13 v1(175.59,168.97) ; U1.H8 v1(170.79,171.37) ; U1.J17 v1(178.79,170.57) ; U1.R9 v1(171.59,164.97)
VDDA: length 4
  TOP w0.127: U1.L21 v1(181.99,168.97)
  TOP w0.381: U1.N21 v1(181.99,166.57) ; U1.G21 v1(181.99,172.17) ; U1.K19 v1(180.39,169.77) ; U1.R21 v1(181.99,164.97) ; U1.J21 v1(181.99,170.57) ; U1.P19 v1(180.39,165.77)
VDDA25: length 1.1
  TOP w0.381: U1.J18 v1(179.59,170.57) ; U1.N18 v1(179.59,166.57)
VDDAUX2: length 2.3
  TOP w0.381: U1.H16 v1(177.99,171.37) ; U1.H14 v1(176.39,171.37) ; U1.H11 v1(173.19,171.37) ; U1.J15 v1(177.19,170.57)
VDDAUX4: length 3
  TOP w0.381: U1.G1 v1(164.9,171.77) ; U1.N9 v1(171.59,166.57) ; U1.K10 v1(172.39,169.77) ; U1.M10 v1(172.39,167.37) ; U1.F4 v1(167.59,172.97)
VDDI0: length 4.2
  TOP w0.127: U1.V8 v1(170.79,162.57)
  TOP w0.381: U1.U1 v1(164.9,163.77) ; U1.W5 v1(168.39,161.77) ; U1.AA9 v1(171.59,160.17) ; U1.U11 v1(173.19,163.37) ; U1.AB6 v1(169.59,159.08) ; U1.Y2 v1(165.99,160.97)
VDDI1: length 4.2
  TOP w0.381: U1.W15 v1(177.19,161.77) ; U1.AA19 v1(180.39,160.17) ; U1.AB16 v1(177.59,159.08) ; U1.Y12 v1(174.79,160.97) ; U1.V18 v1(179.59,162.57) ; U1.T14 v1(176.39,164.17) ; U1.Y22 v1(183.08,161.37)
VDDI2: length 7.6
  TOP w0.381: U1.F14 v1(176.39,172.97) ; U1.B6 v1(169.19,175.37) ; U1.H13 v1(175.59,171.37) ; U1.B16 v1(177.99,176.17) ; U1.A19 v1(179.99,177.27) ; U1.E7 v1(169.99,173.77) ; U1.D10 v1(172.39,174.57) ; U1.H17 v1(178.79,171.37) ; U1.C3 v1(166.79,175.37) ; U1.C21 v1(181.99,175.37) ; U1.C13 v1(175.59,175.37) ; U1.E17 v1(178.79,173.77) ; U1.A9 v1(171.99,177.27)
VDDI3: length 1.1
  TOP w0.381: U1.J11 v1(173.19,170.57) ; U1.G11 v1(173.19,172.17)
VDDI4: length 4
  TOP w0.127: U1.N3 v1(166.79,166.57)
  TOP w0.381: U1.M6 v1(169.19,167.37) ; U1.L9 v1(171.59,168.97) ; U1.T4 v1(167.59,164.17) ; U1.R7 v1(169.99,164.97) ; U1.K2 v1(165.99,169.77) ; U1.J5 v1(168.39,170.57)
VDDSREF: length 1.1
  TOP w0.381: U1.R18 v1(179.59,164.97) ; U1.L18 v1(179.59,168.97)
VSS: length 33.4
  TOP w0.127: U1.G16 v1(177.99,172.17) ; U1.W20 v1(181.19,161.77) ; U1.W10 v1(172.39,161.77)
  TOP w0.381: U1.K7 v1(169.99,169.77) ; U1.E2 v1(165.99,173.77) ; U1.L12 v1(174.79,168.97) ; U1.M17 v1(178.79,167.37) ; U1.N16 v1(177.99,166.57) ; U1.C8 v1(170.79,175.37) ; U1.T9 v1(171.59,164.17) ; U1.N10 v1(172.39,166.57) ; U1.AB11 v1(173.59,159.08) ; U1.A14 v1(175.99,177.27) ; U1.K17 v1(178.79,169.77) ; U1.M11 v1(173.19,167.37) ; U1.Y7 v1(169.99,160.97) ; U1.P5 v1(168.39,165.77) ; U1.G6 v1(169.19,172.17) ; U1.H3 v1(166.79,171.37) ; U1.M15 v1(177.19,167.37) ; U1.R2 v1(165.99,164.97) ; U1.Y17 v1(178.79,160.97) ; U1.AA4 v1(167.59,160.17) ; U1.V13 v1(175.59,162.57) ; U1.A1 v1(165.59,177.27) ; U1.P11 v1(173.19,165.77) ; U1.K15 v1(177.19,169.77) ; U1.E12 v1(174.79,173.77) ; U1.J14 v1(176.39,170.57) ; U1.A22 v1(182.39,177.27) ; U1.K13 v1(175.59,169.77) ; U1.J16 v1(177.99,170.57) ; U1.A4 v1(167.99,177.27) ; U1.P13 v1(175.59,165.77) ; U1.V3 v1(166.79,162.57) ; U1.N12 v1(174.79,166.57) ; U1.AB22 v1(182.39,159.08) ; U1.AA14 v1(176.39,160.17) ; U1.L4 v1(167.59,168.97) ; U1.D15 v1(177.19,174.57) ; U1.B11 v1(173.19,176.17) ; U1.P17 v1(178.79,165.77) ; U1.L16 v1(177.99,168.97) ; U1.L14 v1(176.39,168.97) ; U1.P15 v1(177.19,165.77) ; U1.M13 v1(175.59,167.37) ; U1.K11 v1(173.19,169.77) ; U1.L10 v1(172.39,168.97) ; U1.J12 v1(174.79,170.57) ; U1.AB1 v1(164.9,159.77) ; U1.C18 v1(179.59,175.37) ; U1.U16 v1(177.99,163.37) ; U1.J10 v1(172.39,170.57) ; U1.M1 v1(164.9,167.77) ; U1.U6 v1(169.19,163.37) ; U1.D5 v1(168.39,174.57) ; U1.F9 v1(171.59,172.97)
VSSA: length 15.6
  TOP w0.381: U1.R22 v1(183.08,165.37) ; U1.T18 v1(179.59,164.17) ; U1.M19 v1(179.59,168.18) ; U1.M18 v1(179.59,167.37) ; U1.T19 v1(180.39,164.17) ; U1.L22 v1(183.08,168.57) ; U1.E21 v1(181.99,173.77) ; U1.E20 v1(181.19,173.77) ; U1.U22 v1(183.08,163.77) ; U1.J22 v1(183.08,170.17) ; U1.U20 v1(181.19,163.37) ; U1.G22 v1(183.08,171.77) ; U1.F20 v1(181.19,172.97) ; U1.T20 v1(181.19,164.17) ; U1.E22 v1(183.08,173.37) ; U1.F18 v1(179.59,172.97) ; U1.K18 v1(179.59,169.77) ; U1.P18 v1(179.59,165.77) ; U1.F19 v1(180.39,172.97) ; U1.H20 v1(181.19,171.37) ; U1.P20 v1(181.19,165.77) ; U1.G18 v1(179.59,172.17) ; U1.N22 v1(183.08,166.97) ; U1.U21 v1(181.99,163.37) ; U1.M20 v1(180.39,168.18) ; U1.K20 v1(181.19,169.77)
IO-BANK0_1: length 7.6
  TOP w0.127: U1.R10 v1(172.39,164.97)
  SIG2 w0.076: 173.1,159.06 173.1,160.67 173.63,161.2 173.63,164.35 173.41,164.57 172.79,164.57 v1(172.39,164.97)
IO-BANK0_2: length 6.5
  TOP w0.127: U1.R11 v1(173.19,164.97)
  SIG2 w0.076: 173.87,159.51 173.87,164.64 173.54,164.97 v1(173.19,164.97)
IO-BANK0_3: length 6.3
  TOP w0.127: U1.R12 v1(174.79,164.97)
  SIG2 w0.076: v1(174.79,164.97) 174.11,164.3 174.11,159.51
IO-BANK0_4: length 7.2
  TOP w0.127: U1.T6 v1(169.19,164.17)
  SIG1 w0.076: 164.52,161.58 167.63,161.58 168.19,162.15 168.61,162.15 168.78,162.31 168.78,163.76 v1(169.19,164.17)
IO-BANK0_5: length 7.1
  TOP w0.127: U1.T7 v1(169.99,164.17)
  SIG2 w0.076: v1(169.99,164.17) 169.58,163.76 169.58,160.47 169.25,160.13 169.25,158.44 169.58,158.1
IO-BANK0_6: length 6
  TOP w0.127: U1.T8 v1(170.79,164.17)
  SIG2 w0.076: v1(170.79,164.17) 170.37,163.75 170.37,158.87
IO-BANK0_7: length 6.1
  TOP w0.127: U1.T10 v1(172.39,164.17)
  SIG2 w0.076: v1(172.39,164.17) 172.8,163.76 172.8,158.83
IO-BANK0_8: length 6.5
  TOP w0.127: U1.T11 v1(173.19,164.17)
  SIG1 w0.076: v1(173.19,164.17) 173.19,164.08 174,163.28 174,160.4 174.43,159.97 174.43,158.75
IO-BANK0_9: length 2.2
  TOP w0.076: 164.37,163.39 165.1,163.39 165.18,163.46 165.76,163.46 166.08,163.77 U1.U2
IO-BANK0_10: length 3
  TOP w0.076: 164.4,163.18 165.12,163.18 165.25,163.31 165.98,163.31 166.09,163.42 166.83,163.42 U1.U3
IO-BANK0_11: length 3.9
  TOP w0.127: U1.U4 v1(167.59,163.37)
  SIG1 w0.076: v1(167.59,163.37) 165.86,163.37 165.34,162.85 164.52,162.85
IO-BANK0_12: length 4.8
  TOP w0.127: U1.U5 v1(168.39,163.37)
  SIG1 w0.076: 164.48,162.6 165.57,162.6 165.95,162.99 168,162.99 v1(168.39,163.37)
IO-BANK0_13: length 5.4
  TOP w0.127: U1.U7 v1(169.99,163.37)
  SIG1 w0.076: 170.56,158.76 170.56,161.27 170.37,161.46 170.37,162.99 v1(169.99,163.37)
IO-BANK0_14: length 5.3
  TOP w0.127: U1.U8 v1(170.79,163.37)
  SIG2 w0.076: v1(170.79,163.37) 171.19,162.97 171.19,158.83
IO-BANK0_15: length 5.5
  TOP w0.127: U1.U9 v1(171.59,163.37)
  SIG1 w0.076: 172.4,158.76 172.4,160.69 171.98,161.1 171.98,162.98 v1(171.59,163.37)
IO-BANK0_16: length 6.5
  TOP w0.127: U1.U10 v1(172.39,163.37)
  SIG1 w0.076: v1(172.39,163.37) 172.39,163.37 172.76,162.99 173.48,162.99 173.79,162.68 173.79,160.16 174.23,159.72 174.23,158.6
IO-BANK0_17: length 1.2
  TOP w0.076: U1.V1 164.39,162.97
IO-BANK0_18: length 2.1
  TOP w0.076: U1.V2 166.07,162.66 164.41,162.66
IO-BANK0_19: length 3.8
  TOP w0.127: U1.V4 v1(167.59,162.57)
  SIG1 w0.076: 164.52,162.22 167.24,162.22 v1(167.59,162.57)
IO-BANK0_20: length 4.7
  TOP w0.127: U1.V5 v1(168.39,162.57)
  SIG1 w0.076: v1(168.39,162.57) 168.15,162.57 167.52,161.95 164.55,161.95
IO-BANK0_21: length 4.7
  TOP w0.127: U1.V6 v1(169.19,162.57)
  SIG1 w0.076: 168.48,158.7 168.48,159.89 168.78,160.19 168.78,161.98 169.19,162.38 v1(169.19,162.57)
IO-BANK0_22: length 4.8
  TOP w0.127: U1.V7 v1(169.99,162.57)
  SIG1 w0.076: 170,158.67 170,159.34 169.62,159.73 169.62,162.2 v1(169.99,162.57)
IO-BANK0_23: length 4.6
  TOP w0.127: U1.V9 v1(171.59,162.57)
  SIG1 w0.076: 171.18,158.75 171.18,162.17 v1(171.59,162.57)
IO-BANK0_24: length 4.5
  TOP w0.127: U1.V10 v1(172.39,162.57)
  SIG1 w0.076: v1(172.39,162.57) 172.79,162.17 172.79,158.77
IO-BANK0_25: length 4.9
  TOP w0.127: U1.V11 v1(173.19,162.57)
  SIG1 w0.076: 174.01,158.58 174.01,159.44 173.61,159.84 173.61,162.16 v1(173.19,162.57)
IO-BANK0_26: length 1.2
  TOP w0.076: U1.W1 164.39,162.17
IO-BANK0_27: length 2.1
  TOP w0.076: 164.39,162.49 166.07,162.49 U1.W2
IO-BANK0_28: length 2.9
  TOP w0.076: U1.W3 166.88,162.17 166.56,161.86 164.41,161.86
IO-BANK0_29: length 3.8
  TOP w0.076: U1.W4 167.63,161.82 166.89,161.82 166.78,161.71 164.41,161.71
IO-BANK0_30: length 3.7
  TOP w0.127: U1.W6 v1(169.19,161.77)
  SIG1 w0.076: v1(169.19,161.77) 169.19,160.06 168.85,159.71 168.85,158.76
IO-BANK0_31: length 3.8
  TOP w0.127: U1.W7 v1(169.99,161.77)
  SIG1 w0.076: 170.36,158.72 170.36,161.17 169.99,161.54 v1(169.99,161.77)
IO-BANK0_32: length 3.6
  TOP w0.127: U1.W8 v1(170.79,161.77)
  SIG1 w0.076: v1(170.79,161.77) 170.79,158.72
IO-BANK0_33: length 3.9
  TOP w0.127: U1.W9 v1(171.59,161.77)
  SIG1 w0.076: 172.06,158.67 172.06,160.5 171.59,160.97 v1(171.59,161.77)
IO-BANK0_34: length 3.5
  TOP w0.127: U1.W11 v1(173.19,161.77)
  SIG1 w0.076: v1(173.19,161.77) 173.19,158.87
IO-BANK0_35: length 1.2
  TOP w0.076: U1.Y1 164.39,161.37
IO-BANK0_36: length 3.4
  TOP w0.076: U1.Y3 166.72,160.9 166.72,160.38 166.5,160.15 166.25,160.15 165.99,159.9 165.99,158.65
IO-BANK0_37: length 3.6
  TOP w0.076: U1.Y4 167.59,160.97 167.14,160.97 166.87,160.7 166.87,160.28 166.71,160.11 166.71,159.49 166.62,159.41 166.62,158.58
IO-BANK0_38: length 3
  TOP w0.076: 168.31,158.54 168.31,160.89 U1.Y5
IO-BANK0_39: length 3
  TOP w0.076: U1.Y6 169.12,160.9 169.12,159.53 168.98,159.4 168.98,158.59
IO-BANK0_40: length 3
  TOP w0.076: 170.72,158.56 170.72,160.91 U1.Y8
IO-BANK0_41: length 3
  TOP w0.076: 172.32,158.55 172.32,161.05 172,161.37 U1.Y9
IO-BANK0_42: length 3
  TOP w0.076: 172.47,158.55 172.47,161.05 U1.Y10
IO-BANK0_43: length 2.9
  TOP w0.076: U1.Y11 173.91,161.06 173.91,159.3 173.97,159.23 173.97,158.63
IO-BANK0_44: length 1.2
  TOP w0.076: U1.AA1 164.39,160.57
IO-BANK0_45: length 2.2
  TOP w0.076: U1.AA2 166,160.18 164.35,160.18
IO-BANK0_46: length 2.1
  TOP w0.076: 166.87,158.57 166.87,160 167.19,160.32 U1.AA3
IO-BANK0_47: length 2.1
  TOP w0.076: 168.48,158.57 168.48,160.26 U1.AA5
IO-BANK0_48: length 2.2
  TOP w0.076: 169.19,158.57 169.19,159.26 169.28,159.35 169.28,160.26 U1.AA6
IO-BANK0_49: length 2.2
  TOP w0.076: U1.AA7 170,160.18 170,158.57
IO-BANK0_50: length 2.1
  TOP w0.076: U1.AA8 170.88,160.26 170.88,158.57
IO-BANK0_51: length 2.2
  TOP w0.076: 172.98,158.59 172.98,159.42 173.11,159.55 173.11,160.26 U1.AA10
IO-BANK0_52: length 2.2
  TOP w0.076: 173.16,158.56 173.16,159.31 173.28,159.42 173.28,160.26 U1.AA11
IO-BANK0_53: length 1.2
  TOP w0.076: U1.AB2 166.39,158.6
IO-BANK0_54: length 1.2
  TOP w0.076: U1.AB3 167.19,158.6
IO-BANK0_55: length 1.2
  TOP w0.076: U1.AB4 167.99,158.6
IO-BANK0_56: length 1.2
  TOP w0.076: U1.AB5 168.79,158.6
IO-BANK0_57: length 1.2
  TOP w0.076: U1.AB7 170.39,158.6
IO-BANK0_58: length 1.2
  TOP w0.076: U1.AB8 171.19,158.6
IO-BANK0_59: length 1.2
  TOP w0.076: U1.AB9 171.99,158.6
IO-BANK0_60: length 1.2
  TOP w0.076: U1.AB10 172.79,158.6
IO-BANK1_1: length 6.8
  TOP w0.127: U1.R13 v1(175.59,164.97)
  SIG2 w0.076: v1(175.59,164.97) 176,164.56 176,158.87
IO-BANK1_2: length 7.6
  TOP w0.127: U1.R14 v1(176.39,164.97)
  SIG2 w0.076: 177.03,158.82 177.03,159.46 177.6,160.03 177.6,163.49 177.35,163.74 177.03,163.74 176.76,164 176.76,164.6 v1(176.39,164.97)
IO-BANK1_3: length 7
  TOP w0.127: U1.R15 v1(177.19,164.97)
  SIG2 w0.076: 183.41,164.54 177.62,164.54 v1(177.19,164.97)
IO-BANK1_4: length 6.3
  TOP w0.127: U1.R16 v1(177.99,164.97)
  SIG2 w0.076: v1(177.99,164.97) 178.38,165.37 182.34,165.37 182.73,164.98 183.4,164.98
IO-BANK1_5: length 6
  TOP w0.127: U1.T12 v1(174.79,164.17)
  SIG2 w0.076: v1(174.79,164.17) 174.36,163.75 174.36,160.78 174.69,160.46 174.69,159.08
IO-BANK1_6: length 6
  TOP w0.127: U1.T13 v1(175.59,164.17)
  SIG2 w0.076: v1(175.59,164.17) 175.2,163.78 175.2,158.88
IO-BANK1_7: length 6.9
  TOP w0.127: U1.T15 v1(177.19,164.17)
  SIG2 w0.076: 178.06,158.76 178.06,159.44 178.38,159.76 178.38,163.51 178.12,163.78 177.59,163.78 v1(177.19,164.17)
IO-BANK1_8: length 6.7
  TOP w0.127: U1.T16 v1(177.99,164.17)
  SIG2 w0.076: v1(177.99,164.17) 178.15,164.17 178.54,163.78 182.25,163.78 182.84,163.18 183.69,163.18
IO-BANK1_9: length 6.2
  TOP w0.127: U1.T17 v1(178.79,164.17)
  SIG1 w0.076: 183.45,162.65 180.12,162.65 179.79,162.98 179.44,162.98 179.19,163.23 179.19,163.81 178.82,164.17 v1(178.79,164.17)
IO-BANK1_10: length 5.7
  TOP w0.127: U1.U12 v1(174.79,163.37)
  SIG1 w0.076: v1(174.79,163.37) 174.75,163.37 174.19,162.81 174.19,160.61 174.66,160.14 174.66,158.69
IO-BANK1_11: length 5.3
  TOP w0.127: U1.U13 v1(175.59,163.37)
  SIG1 w0.076: 175.19,158.79 175.19,162.97 v1(175.59,163.37)
IO-BANK1_12: length 5.4
  TOP w0.127: U1.U14 v1(176.39,163.37)
  SIG2 w0.076: 176.58,158.85 176.58,159.6 176.8,159.81 176.8,162.97 v1(176.39,163.37)
IO-BANK1_13: length 5.6
  TOP w0.127: U1.U15 v1(177.19,163.37)
  SIG1 w0.076: 177.15,158.71 177.15,159.74 177.56,160.15 177.56,163 v1(177.19,163.37)
IO-BANK1_14: length 6.1
  TOP w0.127: U1.U17 v1(178.79,163.37)
  SIG1 w0.076: v1(178.79,163.37) 179.15,163.01 179.15,162.43 179.39,162.19 183.47,162.19
IO-BANK1_15: length 4.6
  TOP w0.127: U1.U18 v1(179.59,163.37)
  SIG1 w0.076: 183.45,162.98 180.19,162.98 179.8,163.37 v1(179.59,163.37)
IO-BANK1_16: length 4
  TOP w0.127: U1.U19 v1(180.39,163.37)
  SIG1 w0.076: 183.44,163.36 182.64,163.36 182.22,163.78 180.8,163.78 v1(180.39,163.37)
IO-BANK1_17: length 4.7
  TOP w0.127: U1.V12 v1(174.79,162.57)
  SIG1 w0.076: 174.89,158.87 174.89,160.22 174.36,160.74 174.36,162.15 v1(174.79,162.57)
IO-BANK1_18: length 4.7
  TOP w0.127: U1.V14 v1(176.39,162.57)
  SIG1 w0.076: 175.6,158.73 175.6,161.14 175.98,161.51 175.98,162.16 v1(176.39,162.57)
IO-BANK1_19: length 4.5
  TOP w0.127: U1.V15 v1(177.19,162.57)
  SIG1 w0.076: 176.81,158.77 176.81,162.19 v1(177.19,162.57)
IO-BANK1_20: length 4.6
  TOP w0.127: U1.V16 v1(177.99,162.57)
  SIG1 w0.076: v1(177.99,162.57) 178.37,162.19 178.37,161.46 178.22,161.31 178.22,158.75
IO-BANK1_21: length 4.5
  TOP w0.127: U1.V17 v1(178.79,162.57)
  SIG1 w0.076: 179.18,158.79 179.18,161.99 178.79,162.38 v1(178.79,162.57)
IO-BANK1_22: length 4.2
  TOP w0.076: 183.48,161.97 182.75,161.97 182.64,161.86 182.2,161.86 181.98,162.08 181.98,162.35 181.82,162.51 180.46,162.51 U1.V19
IO-BANK1_23: length 2.9
  TOP w0.076: 183.51,162.5 182.07,162.5 181.91,162.66 181.1,162.66 U1.V20
IO-BANK1_24: length 2
  TOP w0.076: 183.49,162.66 182.22,162.66 181.91,162.97 U1.V21
IO-BANK1_25: length 1.1
  TOP w0.076: U1.V22 183.48,162.97
IO-BANK1_26: length 3.7
  TOP w0.076: U1.W12 174.07,161.85 174.07,159.45 174.18,159.33 174.18,158.63
IO-BANK1_27: length 3.7
  TOP w0.127: U1.W13 v1(175.59,161.77)
  SIG1 w0.076: v1(175.59,161.77) 175.38,161.56 175.38,158.77
IO-BANK1_28: length 3.8
  TOP w0.127: U1.W14 v1(176.39,161.77)
  SIG1 w0.076: 175.83,158.75 175.83,160.98 176.39,161.54 v1(176.39,161.77)
IO-BANK1_29: length 3.6
  TOP w0.127: U1.W16 v1(177.99,161.77)
  SIG1 w0.076: v1(177.99,161.77) 177.99,158.76
IO-BANK1_30: length 3.7
  TOP w0.127: U1.W17 v1(178.79,161.77)
  SIG1 w0.076: 178.42,158.76 178.42,161.17 178.79,161.54 v1(178.79,161.77)
IO-BANK1_31: length 3.5
  TOP w0.127: U1.W18 v1(179.59,161.77)
  SIG1 w0.076: v1(179.59,161.77) 179.59,158.79
IO-BANK1_32: length 4.3
  TOP w0.076: U1.W19 180.39,161.77 180.39,161.12 180.56,160.95 180.91,160.95 181.16,160.71 181.16,160.47 181.27,160.36 181.27,158.61 181.29,158.59
IO-BANK1_33: length 2.2
  TOP w0.076: 183.52,161.78 182.81,161.78 182.74,161.71 182.06,161.71 U1.W21
IO-BANK1_34: length 1.1
  TOP w0.076: U1.W22 183.48,162.17
IO-BANK1_35: length 3
  TOP w0.076: U1.Y13 175.66,160.91 175.66,158.56
IO-BANK1_36: length 2.9
  TOP w0.127: U1.Y14 v1(176.39,160.97)
  SIG1 w0.076: 176.03,158.79 176.03,160.61 v1(176.39,160.97)
IO-BANK1_37: length 2.9
  TOP w0.076: 177.21,158.68 177.21,159.28 177.27,159.34 177.27,160.89 U1.Y15
IO-BANK1_38: length 3
  TOP w0.076: U1.Y16 177.98,160.98 177.98,160.2 178.07,160.1 178.07,159.52 178.19,159.41 178.19,158.66
IO-BANK1_39: length 2.9
  TOP w0.076: 179.52,158.58 179.52,161.04 U1.Y18
IO-BANK1_40: length 2.9
  TOP w0.076: 179.67,158.58 179.67,161.06 U1.Y19
IO-BANK1_41: length 3
  TOP w0.076: U1.Y20 181.27,160.89 182.69,160.89 182.82,160.76 183.52,160.76
IO-BANK1_42: length 2.1
  TOP w0.076: 183.52,160.96 182.93,160.96 182.83,161.06 181.9,161.06 U1.Y21
IO-BANK1_43: length 2.2
  TOP w0.076: U1.AA12 174.8,160.16 174.8,158.57
IO-BANK1_44: length 2.1
  TOP w0.076: 175.5,158.57 175.5,160.26 U1.AA13
IO-BANK1_45: length 2.1
  TOP w0.076: U1.AA15 177.1,160.26 177.1,159.48 177,159.38 177,158.67
IO-BANK1_46: length 2.1
  TOP w0.076: 178.01,158.63 178.01,159.27 177.92,159.35 177.92,159.97 177.59,160.3 U1.AA16
IO-BANK1_47: length 2.1
  TOP w0.076: 178.71,158.57 178.71,160.25 U1.AA17
IO-BANK1_48: length 2.1
  TOP w0.076: 178.87,158.57 178.87,160.26 U1.AA18
IO-BANK1_49: length 2.1
  TOP w0.076: U1.AA20 181.11,160.25 181.11,158.57
IO-BANK1_50: length 2.1
  TOP w0.076: U1.AA21 182,160.16 183.56,160.16
IO-BANK1_51: length 1.2
  TOP w0.076: U1.AA22 183.56,160.57
IO-BANK1_52: length 1.1
  TOP w0.076: U1.AB12 174.39,158.68
IO-BANK1_53: length 1.1
  TOP w0.076: U1.AB13 175.19,158.68
IO-BANK1_54: length 1.1
  TOP w0.076: U1.AB14 175.99,158.72
IO-BANK1_55: length 1.1
  TOP w0.076: U1.AB15 176.79,158.68
IO-BANK1_56: length 1.1
  TOP w0.076: U1.AB17 178.39,158.68
IO-BANK1_57: length 1.1
  TOP w0.076: U1.AB18 179.19,158.68
IO-BANK1_58: length 1.1
  TOP w0.076: U1.AB19 179.99,158.63
IO-BANK1_59: length 1.1
  TOP w0.076: U1.AB20 180.79,158.68
IO-BANK1_60: length 1.1
  TOP w0.076: U1.AB21 181.59,158.68
IO-BANK2_1: length 1.3
  TOP w0.076: U1.A2 166.39,177.88
IO-BANK2_2: length 1.3
  TOP w0.076: U1.A3 167.1,176.66 167.1,177.88
IO-BANK2_3: length 1.3
  TOP w0.076: U1.A5 168.79,177.88
IO-BANK2_4: length 1.3
  TOP w0.076: U1.A6 169.59,177.88
IO-BANK2_5: length 1.3
  TOP w0.076: U1.A7 170.39,177.88
IO-BANK2_6: length 1.3
  TOP w0.076: U1.A8 171.19,177.88
IO-BANK2_7: length 1.3
  TOP w0.076: U1.A10 172.79,177.88
IO-BANK2_8: length 1.3
  TOP w0.076: U1.A11 173.59,177.86
IO-BANK2_9: length 1.3
  TOP w0.076: U1.A12 174.39,177.88
IO-BANK2_10: length 1.3
  TOP w0.076: U1.A13 175.19,177.86
IO-BANK2_11: length 1.3
  TOP w0.076: U1.A15 176.79,177.88
IO-BANK2_12: length 1.3
  TOP w0.076: U1.A16 177.59,177.88
IO-BANK2_13: length 1.3
  TOP w0.076: U1.A17 178.39,177.88
IO-BANK2_14: length 1.3
  TOP w0.076: U1.A18 179.19,177.88
IO-BANK2_15: length 1.3
  TOP w0.076: U1.A20 180.79,177.88
IO-BANK2_16: length 1.3
  TOP w0.076: U1.A21 181.59,177.86
IO-BANK2_17: length 1.2
  TOP w0.076: U1.B1 164.39,175.77
IO-BANK2_18: length 2.3
  TOP w0.076: 166.72,177.89 166.72,176.11 U1.B2
IO-BANK2_19: length 2.2
  TOP w0.076: U1.B3 166.88,176.09 166.88,177.89
IO-BANK2_20: length 2.3
  TOP w0.076: U1.B4 168.32,176.11 168.32,177.03 168.38,177.08 168.38,177.87
IO-BANK2_21: length 2.3
  TOP w0.076: 169.24,177.88 169.24,176.22 U1.B5
IO-BANK2_22: length 2.2
  TOP w0.076: U1.B7 170.71,176.09 170.71,177.88
IO-BANK2_23: length 2.2
  TOP w0.076: U1.B8 170.87,176.1 170.87,177.88
IO-BANK2_24: length 2.3
  TOP w0.076: U1.B9 171.68,176.09 171.68,177.01 171.57,177.12 171.57,177.88
IO-BANK2_25: length 2.2
  TOP w0.076: U1.B10 172.48,176.09 172.48,176.74 172.62,176.88 172.62,177.83
IO-BANK2_26: length 2.2
  TOP w0.076: 174.7,177.86 174.7,176.34 174.39,176.03 U1.B12
IO-BANK2_27: length 2.3
  TOP w0.076: U1.B13 175.19,175.78 175.67,176.26 175.67,177.02 175.6,177.09 175.6,177.86
IO-BANK2_28: length 2.2
  TOP w0.076: 176.39,177.84 176.39,177.02 176.3,176.93 176.3,176.09 U1.B14
IO-BANK2_29: length 2.2
  TOP w0.076: 177.11,177.88 177.11,176.09 U1.B15
IO-BANK2_30: length 2.3
  TOP w0.076: U1.B17 178.39,176.07 178.71,176.39 178.71,177.9
IO-BANK2_31: length 2.3
  TOP w0.076: U1.B18 179.66,176.24 179.66,176.87 179.6,176.93 179.6,177.87
IO-BANK2_32: length 2.3
  TOP w0.076: 180.4,177.89 180.4,177.02 180.3,176.92 180.3,176.39 179.99,176.07 U1.B19
IO-BANK2_33: length 2.3
  TOP w0.076: 181.26,177.9 181.26,176.24 U1.B20
IO-BANK2_34: length 2.7
  TOP w0.076: 184.15,176.17 181.99,176.17 U1.B21
IO-BANK2_35: length 1.3
  TOP w0.076: U1.B22 183.7,175.77
IO-BANK2_36: length 1.2
  TOP w0.076: U1.C1 164.39,174.97
IO-BANK2_37: length 3
  TOP w0.076: U1.C2 166,175.36 166,177.82
IO-BANK2_38: length 3
  TOP w0.076: 167.52,177.81 167.52,177.08 167.68,176.93 167.68,175.29 U1.C4
IO-BANK2_39: length 3.1
  TOP w0.076: 168.57,177.85 168.57,176.94 168.48,176.84 168.48,175.29 U1.C5
IO-BANK2_40: length 3.1
  TOP w0.076: 169.91,177.89 169.91,175.29 U1.C6
IO-BANK2_41: length 3
  TOP w0.076: 170.08,177.88 170.08,175.29 U1.C7
IO-BANK2_42: length 3.1
  TOP w0.076: U1.C9 171.51,175.46 171.51,176.85 171.37,176.98 171.37,177.87
IO-BANK2_43: length 3.1
  TOP w0.076: 172.41,177.84 172.41,176.96 172.32,176.87 172.32,175.44 U1.C10
IO-BANK2_45: length 3.1
  TOP w0.076: U1.C12 174.06,175.3 174.06,177.9
IO-BANK2_46: length 3.1
  TOP w0.076: 176.59,177.85 176.59,176.91 176.47,176.79 176.47,175.97 176.39,175.88 176.39,175.37 U1.C14
IO-BANK2_47: length 3.1
  TOP w0.076: U1.C15 177.27,175.46 177.27,177.91
IO-BANK2_48: length 3.8
  TOP w0.076: U1.C16 177.98,175.36 178.51,175.36 178.71,175.56 178.71,176.12 178.87,176.28 178.87,177.89
IO-BANK2_49: length 3.6
  TOP w0.076: U1.C17 178.87,175.46 178.87,175.98 179.07,176.18 179.33,176.18 179.5,176.35 179.5,176.79 179.38,176.91 179.38,177.89
IO-BANK2_50: length 3.1
  TOP w0.076: U1.C19 179.99,175.08 180.3,175.39 180.3,176.1 180.46,176.26 180.46,176.84 180.59,176.97 180.59,177.87
IO-BANK2_51: length 2.8
  TOP w0.381: U1.C20 v1(181.19,175.37)
  SIG1 w0.076: v1(181.19,175.37) 181.19,177.59
IO-BANK2_52: length 1.3
  TOP w0.076: U1.C22 183.7,174.97
IO-BANK2_53: length 3.4
  TOP w0.076: 164.37,175.34 165.72,175.34 165.98,175.09 165.98,174.87 166.19,174.66 166.71,174.66 U1.D3
IO-BANK2_54: length 4
  TOP w0.076: 167.32,177.87 167.32,177.03 167.52,176.82 167.52,174.64 U1.D4
IO-BANK2_55: length 4.1
  TOP w0.127: U1.D6 v1(169.19,174.57)
  SIG1 w0.076: 168.73,177.96 168.73,175.28 169.19,174.82 v1(169.19,174.57)
IO-BANK2_56: length 4
  TOP w0.127: U1.D7 v1(169.99,174.57)
  SIG1 w0.076: v1(169.99,174.57) 169.99,178.01
IO-BANK2_57: length 3.9
  TOP w0.127: U1.D8 v1(170.79,174.57)
  SIG1 w0.076: v1(170.79,174.57) 170.79,174.79 171.14,175.14 171.14,177.78
IO-BANK2_58: length 4.2
  TOP w0.127: U1.D9 v1(171.59,174.57)
  SIG1 w0.076: 172.34,177.87 172.34,176.9 171.74,176.3 171.74,174.97 171.59,174.82 v1(171.59,174.57)
IO-BANK2_59: length 3.7
  TOP w0.127: U1.D11 v1(173.19,174.57)
  SIG1 w0.076: v1(173.19,174.57) 173.19,175.43 173.64,175.87 173.64,177.53
IO-BANK2_60: length 3.9
  TOP w0.076: U1.D12 174.39,174.18 174.72,174.51 174.72,176.1 174.87,176.25 174.87,177.86
IO-BANK2_61: length 4.3
  TOP w0.076: U1.D13 174.87,174.49 174.87,175.97 175.08,176.18 175.35,176.18 175.5,176.34 175.5,176.88 175.37,177.01 175.37,177.86
IO-BANK2_62: length 3.6
  TOP w0.127: U1.D14 v1(176.39,174.57)
  SIG1 w0.076: 176.53,177.53 176.53,174.72 v1(176.39,174.57)
IO-BANK2_63: length 3.7
  TOP w0.127: U1.D16 v1(177.99,174.57)
  SIG1 w0.076: v1(177.99,174.57) 177.99,175.39 177.56,175.82 177.56,177.53
IO-BANK2_64: length 3.6
  TOP w0.127: U1.D17 v1(178.79,174.57)
  SIG1 w0.076: v1(178.79,174.57) 178.79,177.58
IO-BANK2_65: length 3.9
  TOP w0.127: U1.D18 v1(179.59,174.57)
  SIG1 w0.076: 179.65,177.56 179.65,176.78 180.02,176.41 180.02,175.01 v1(179.59,174.57)
IO-BANK2_66: length 4.4
  TOP w0.076: U1.D19 180.39,174.57 180.39,175.23 180.47,175.31 180.47,176.03 180.63,176.19 180.93,176.19 181.1,176.36 181.1,177.91
IO-BANK2_67: length 3.1
  TOP w0.076: 183.7,174.66 181.27,174.66 U1.D20
IO-BANK2_68: length 2.2
  TOP w0.076: 183.69,174.5 181.92,174.5 U1.D21
IO-BANK2_69: length 0.9
  TOP w0.076: U1.D22 183.33,174.17
IO-BANK2_70: length 0.6
  TOP w0.127: U1.E4 v1(167.59,173.77)
IO-BANK2_71: length 4.2
  TOP w0.127: U1.E5 v1(168.39,173.77)
  SIG1 w0.076: 164.93,174.18 167.77,174.18 168.18,173.77 v1(168.39,173.77)
IO-BANK2_72: length 5
  TOP w0.127: U1.E6 v1(169.19,173.77)
  SIG1 w0.076: v1(169.19,173.77) 169.19,173.9 168.82,174.26 168.82,174.78 168.43,175.17 168.43,177.93
IO-BANK2_73: length 4.7
  TOP w0.127: U1.E8 v1(170.79,173.77)
  SIG1 w0.076: v1(170.79,173.77) 170.42,174.14 170.42,177.75
IO-BANK2_74: length 5
  TOP w0.127: U1.E9 v1(171.59,173.77)
  SIG1 w0.076: 172.57,177.83 172.57,176.77 172,176.2 172,174.18 v1(171.59,173.77)
IO-BANK2_75: length 5
  TOP w0.127: U1.E10 v1(172.39,173.77)
  SIG1 w0.076: v1(172.39,173.77) 172.77,174.15 172.77,176.53 172.9,176.66 172.9,177.96
IO-BANK2_76: length 4.5
  TOP w0.127: U1.E11 v1(173.19,173.77)
  SIG1 w0.076: v1(173.19,173.77) 173.56,174.14 173.56,175.39 173.82,175.66 173.82,177.46
IO-BANK2_77: length 4.5
  TOP w0.127: U1.E13 v1(175.59,173.77)
  SIG1 w0.076: 175.14,177.5 175.14,174.85 175.45,174.54 175.45,173.91 v1(175.59,173.77)
IO-BANK2_78: length 4.9
  TOP w0.127: U1.E14 v1(176.39,173.77)
  SIG1 w0.076: 175.57,177.51 175.57,176.85 176.26,176.16 176.26,175.1 175.98,174.83 175.98,174.4 176.39,173.99 v1(176.39,173.77)
IO-BANK2_79: length 4.5
  TOP w0.127: U1.E15 v1(177.19,173.77)
  SIG1 w0.076: 176.8,177.51 176.8,174.16 v1(177.19,173.77)
IO-BANK2_80: length 4.6
  TOP w0.127: U1.E16 v1(177.99,173.77)
  SIG1 w0.076: 177.28,177.53 177.28,175.61 177.59,175.3 177.59,174.18 v1(177.99,173.77)
IO-BANK2_81: length 4.9
  TOP w0.127: U1.E18 v1(179.59,173.77)
  SIG1 w0.076: v1(179.59,173.77) 180.61,174.79 183.46,174.79
IO-BANK2_82: length 3.8
  TOP w0.127: U1.E19 v1(180.39,173.77)
  SIG1 w0.076: 183.37,174.41 181.03,174.41 v1(180.39,173.77)
IO-BANK2_83: length 6.4
  TOP w0.127: U1.F10 v1(172.39,172.97)
  SIG1 w0.076: v1(172.39,172.97) 172.41,172.97 172.79,173.36 173.41,173.36 173.75,173.69 173.75,175.22 174.02,175.5 174.02,177.77
IO-BANK2_84: length 6.1
  TOP w0.127: U1.F11 v1(173.19,172.97)
  SIG1 w0.076: v1(173.19,172.97) 173.48,172.97 173.95,173.44 173.95,175.12 174.24,175.4 174.24,177.87
IO-BANK2_85: length 5.4
  TOP w0.127: U1.F12 v1(174.79,172.97)
  SIG1 w0.076: v1(174.79,172.97) 175.2,173.38 175.2,174.35 174.94,174.61 174.94,177.57
IO-BANK2_86: length 5.8
  TOP w0.127: U1.F13 v1(175.59,172.97)
  SIG1 w0.076: v1(175.59,172.97) 176,173.38 176,174.01 175.73,174.28 175.73,174.98 175.99,175.24 175.99,176.01 175.36,176.64 175.36,177.52
IO-BANK2_87: length 5.4
  TOP w0.127: U1.F15 v1(177.19,172.97)
  SIG2 w0.076: 177.57,177.67 177.57,173.35 v1(177.19,172.97)
IO-BANK2_88: length 5.3
  TOP w0.127: U1.F16 v1(177.99,172.97)
  SIG1 w0.076: 178.4,177.51 178.4,173.38 v1(177.99,172.97)
IO-BANK2_89: length 5.3
  TOP w0.127: U1.F17 v1(178.79,172.97)
  SIG1 w0.076: v1(178.79,172.97) 179.19,173.37 179.19,177.57
IO-BANK2_90: length 6.2
  TOP w0.127: U1.G12 v1(174.79,172.17)
  SIG1 w0.076: 174.72,177.5 174.72,174.51 174.42,174.21 174.42,172.54 v1(174.79,172.17)
IO-BANK2_91: length 6.9
  TOP w0.127: U1.G13 v1(175.59,172.17)
  SIG2 w0.076: 174.3,177.57 174.3,172.75 174.51,172.54 175.22,172.54 v1(175.59,172.17)
IO-BANK2_92: length 6.3
  TOP w0.127: U1.G14 v1(176.39,172.17)
  SIG2 w0.076: 175.55,177.56 175.55,176.1 176.01,175.63 176.01,172.55 v1(176.39,172.17)
IO-BANK2_93: length 7.1
  TOP w0.127: U1.G15 v1(177.19,172.17)
  SIG2 w0.076: 183.42,171.36 181.97,171.36 181.55,171.78 177.58,171.78 v1(177.19,172.17)
IO-BANK2_94: length 6.4
  TOP w0.127: U1.G17 v1(178.79,172.17)
  SIG1 w0.076: 183.54,174.06 182.94,174.06 182.24,173.36 180.15,173.36 179.99,173.2 179.99,172.75 179.79,172.55 179.17,172.55 178.8,172.17 v1(178.79,172.17)
IO-BANK2_95: length 7.1
  TOP w0.127: U1.H12 v1(174.79,171.37)
  SIG1 w0.076: v1(174.79,171.37) 174.2,171.96 174.2,174.98 174.46,175.24 174.46,177.55
IO-BANK2_96: length 6.9
  TOP w0.127: U1.H15 v1(177.19,171.37)
  SIG2 w0.076: v1(177.19,171.37) 177.58,170.98 183.38,170.98
IO-BANK4_1: length 1.2
  TOP w0.076: U1.H1 164.39,170.97
IO-BANK4_2: length 2.2
  TOP w0.076: 164.39,171.37 165.16,171.37 165.22,171.44 165.92,171.44 U1.H2
IO-BANK4_3: length 1.2
  TOP w0.076: U1.J1 164.39,170.17
IO-BANK4_4: length 2.1
  TOP w0.076: 164.39,170.49 165.83,170.49 166.14,170.17 U1.J2
IO-BANK4_5: length 3
  TOP w0.076: 164.39,170.64 165.95,170.64 166.1,170.49 166.88,170.49 U1.J3
